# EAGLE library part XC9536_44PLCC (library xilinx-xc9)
xc9536_pc44 XC9500 In-System Programmable CPLD Family Auto generated by make-symbol-device-package-bsdl.ulp Rev. 34 Source: xc9536_pc44.bsd
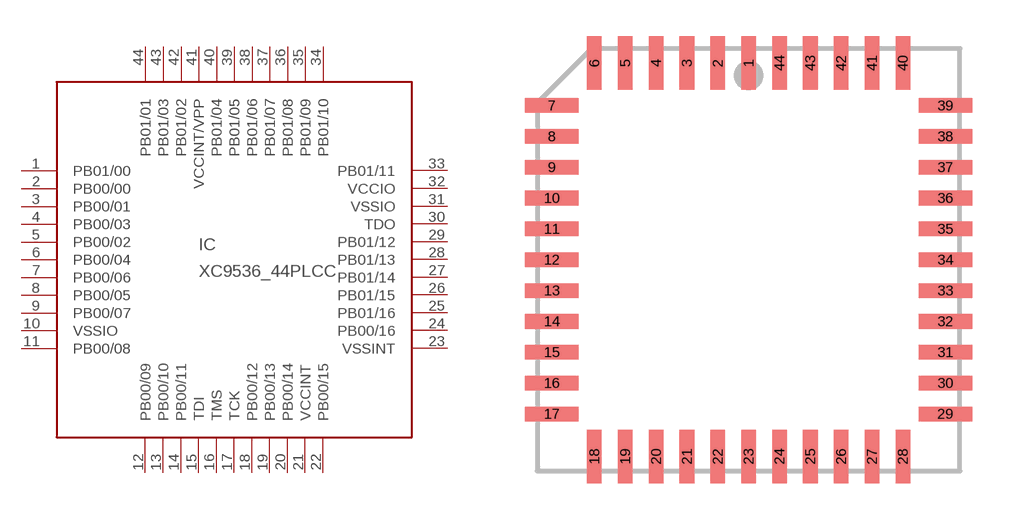
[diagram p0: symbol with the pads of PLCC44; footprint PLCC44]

Designator prefix IC

## XC9536_44PLCC (MPN: XC9536-15PCG44C; OC_FARNELL: 1193226; OC_NEWARK: 98K3376)  [PLCC44]
1  PB01/00
2  PB00/00
3  PB00/01
4  PB00/03
5  PB00/02
6  PB00/04
7  PB00/06
8  PB00/05
9  PB00/07
10  VSSIO  pwr
11  PB00/08
12  PB00/09
13  PB00/10
14  PB00/11
15  TDI  in
16  TMS  in
17  TCK  in
18  PB00/12
19  PB00/13
20  PB00/14
21  VCCINT  pwr
22  PB00/15
23  VSSINT  pwr
24  PB00/16
25  PB01/16
26  PB01/15
27  PB01/14
28  PB01/13
29  PB01/12
30  TDO  out
31  VSSIO  pwr
32  VCCIO  pwr
33  PB01/11
34  PB01/10
35  PB01/09
36  PB01/08
37  PB01/07
38  PB01/06
39  PB01/05
40  PB01/04
41  VCCINT/VPP  in
42  PB01/02
43  PB01/03
44  PB01/01

## Footprint PLCC44 (pad centres in mm)
PLASTIC LEADED CHIP CARRIER square
smd 0.6 x 2.2: 1 0,8.1; 2 -1.27,8.1; 3 -2.54,8.1; 4 -3.81,8.1; 5 -5.08,8.1; 6 -6.35,8.1; 18 -6.35,-8.1; 19 -5.08,-8.1; 20 -3.81,-8.1; 21 -2.54,-8.1; 22 -1.27,-8.1; 23 0,-8.1; 24 1.27,-8.1; 25 2.54,-8.1; 26 3.81,-8.1; 27 5.08,-8.1; 28 6.35,-8.1; 40 6.35,8.1; 41 5.08,8.1; 42 3.81,8.1; 43 2.54,8.1; 44 1.27,8.1
smd 2.2 x 0.6: 7 -8.1,6.35; 8 -8.1,5.08; 9 -8.1,3.81; 10 -8.1,2.54; 11 -8.1,1.27; 12 -8.1,0; 13 -8.1,-1.27; 14 -8.1,-2.54; 15 -8.1,-3.81; 16 -8.1,-5.08; 17 -8.1,-6.35; 29 8.1,-6.35; 30 8.1,-5.08; 31 8.1,-3.81; 32 8.1,-2.54; 33 8.1,-1.27; 34 8.1,0; 35 8.1,1.27; 36 8.1,2.54; 37 8.1,3.81; 38 8.1,5.08; 39 8.1,6.35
